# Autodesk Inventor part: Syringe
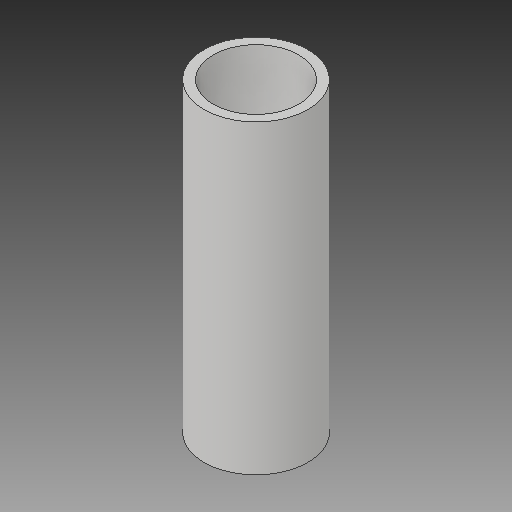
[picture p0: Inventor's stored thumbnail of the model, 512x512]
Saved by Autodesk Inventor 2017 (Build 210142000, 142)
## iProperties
Created: 2020-03
Part Number: Syringe
Material: Generic
Document SubType Name: Modeling
Designer: user
Density: 1 g/cm^3
Appearance: Default
Author: user
Revision Number: ANY
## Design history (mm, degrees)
feature "Revolve1"
body "Solid1"
